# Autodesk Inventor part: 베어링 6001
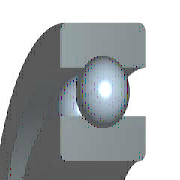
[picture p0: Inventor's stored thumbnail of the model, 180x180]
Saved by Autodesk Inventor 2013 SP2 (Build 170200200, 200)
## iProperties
Created: 2012-02
Part Number: 베어링 6001
Material: 강철, 연강
Description: 깊은 그루브 볼 베어링
Document SubType Name: Modeling
Standard: KS B 2023
Designer: mduedu
Standards Organization: KS
Language: ko-KR
Size Designation: 6001 - 12 x 28 x 8
Categories: <MemberInstance><Categories><Category DisplayName="샤프트 부품" InternalName="7f7aeb1f-a693-4053-b835-cee3144e0d98" Mnemonic="SHFT"><Category DisplayName="베어링" Inter
Density: 7.86 g/cm^3
Mass: 21.4855 g
Surface Area: 31.1809 cm^2
Volume: 2.73352 cm^3
IsCustomPart: 1
Author: mduedu
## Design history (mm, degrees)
sketch "스케치" dims "d0" = 4.16 (= -0.26 x WD + 0.26 x BD)
  geometry: L1 (1.92, 10)-(6.08, 10); L2 (4, 10)-(4, 7.92); L3 (4, 10)-(4, 12.08); L4 (2.454, 8.608)-(0, 8.608); L5 (0, 6)-(8, 6); L6 (2.454, 11.392)-(0, 11.392); L7 (0, 14)-(8, 14); L8 (8, 6)-(8, 8.608); L9 (5.546, 8.608)-(8, 8.608); L10 (5.546, 11.392)-(8, 11.392); L11 (8, 14)-(8, 11.392); L12 (-1.4, 0)-(8.4, 0) reference; L13 (0, -0.3)-(0, 5.3) reference
  constraints: 22 end point, 4 point on line, 2 collinear, 2 perpendicular, 2 symmetric about line, 1 midpoint, 1 parallel, 14 other
  dimensions: "d9" = 12 diameter of L5 L12 (= WD); "d11" = 28 diameter of L7 L12 (= BD); "d12" = 8 distance between parallel lines of L8 L13 (= KB); "d13" = 17.216 diameter of L9 L12 (= 0.326 x BD + 0.674 x WD)
revolve "본체" stored, may be unused: angle "d6" = 90 deg
revolve "볼" stored, may be unused: angle "d7" = 90 deg
pattern_circular "IDS_ARRAYBALL[SIMPL:T]" dims angle "d3" = 360 deg
body "Solid1"
fillet "모깎기1" dims "d1" = 0.3 (= KRS)
other parameters: "WD" = 12 [user parameter; used in 5 equation terms], "BD" = 28 [user parameter; used in 5 equation terms], "KB" = 8 [user parameter; used in 1 equation term], "KRS" = 0.3 [user parameter; used in 1 equation term], "d4" = 0, "d5" = 0, "d8" = 0, "d14" = 0, "d15" = 0, "BBA" = 0 [user parameter], "BC0" = 2360000 [user parameter], "BC" = 5070000 [user parameter], "BR" = 14 (= 0.5 x BD) [user parameter], "WR" = 6 (= 0.5 x WD) [user parameter]
